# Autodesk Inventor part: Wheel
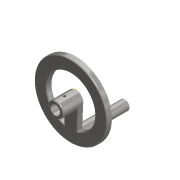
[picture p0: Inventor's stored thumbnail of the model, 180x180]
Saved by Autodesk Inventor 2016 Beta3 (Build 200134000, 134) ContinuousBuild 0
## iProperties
Created: 2016-02
Part Number: Wheel
Material: Stainless Steel
Document SubType Name: Modeling
Designer: Vertex
Density: 8 g/cm^3
Appearance: Semi-Polished
Mass: 759.354 g
Surface Area: 286.814 cm^2
Volume: 94.9192 cm^3
Author: Vertex
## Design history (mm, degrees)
sketch "Sketch1"
  geometry: C1 r 12.5 at (0, 0); 1 further point
  constraints: 1 centre point
  dimensions: "d1" = 25 diameter of C1
extrude "Extrusion1" new body sketch "Sketch1" distance "d2" = 35; taper "d3" = 0 deg
hole "Hole1" diameter "d6" = 16; stored, may be unused: countersink angle "d10" = 90 deg, drill point angle "d12" = 118 deg; dims "d4" = 10, "d5" = 10, "d7" = 7.5, "d8" = 3.75, "d9" = 2.5, "d11" = 30
workplane "Work Plane1"
sketch "Sketch2"
  geometry: L1 (12.5, 35)-(-12.5, 35) reference; C1 r 2.5 at (0, 20); 1 further point
  constraints: 1 centre point
  dimensions: "d14" = 5 diameter of C1; "d15" = 15 distance from line of C1.centre L1
hole "Hole2" sketch "Sketch2" at (0, 20) diameter "d16" = 4.13; stored, may be unused: countersink angle "d20" = 90 deg, drill point angle "d22" = 118 deg; dims "d17" = 10, "d18" = 3.75, "d19" = 2.5, "d21" = 10
sketch "Sketch3"
  geometry: 1 further point
sketch "Sketch4" dims "d29" = 120 (derived)
  geometry: L1 (10.877, -38.493)-(12.489, -0.523); L2 (-10.9, -38.486)-(-12.489, -0.523); A1 r 12.5 centre (0, 0) between (12.489, -0.53) and (-12.489, -0.523); A2 r 40 centre (0, 0) between (10.877, -38.493) and (-10.9, -38.486); 4 further points
  constraints: 5 point on circle, 4 end point, 3 coincident, 2 centre point, 2 vertical alignment, 1 horizontal alignment, 1 point on line, 7 other
  dimensions: "d27" = 60 distance of point (0, 0) point (0, -60); "d30" = 80 diameter of A2; "d31" = 21.77766 distance of L1.start L2.start
extrude "Extrusion2" join sketch "Sketch4" distance "d32" = 10; taper "d33" = 0 deg
fillet "Fillet1" dims "d34" = 2
sketch "Sketch5"
  geometry: C1 r 8 at (0, -50); 1 further point
  constraints: 1 centre point
  dimensions: "d35" = 16 diameter of C1
extrude "Extrusion3" join sketch "Sketch5" distance "d36" = 80; taper "d37" = 0 deg
sketch "Sketch6"
  geometry: C1 r 2.5 at (0, 0); 1 further point
  constraints: 1 centre point
  dimensions: "d38" = 5 diameter of C1
hole "Hole3" sketch "Sketch6" at (0, 0) diameter "d39" = 4.13; stored, may be unused: countersink angle "d43" = 90 deg, drill point angle "d45" = 118 deg; dims "d40" = 10, "d41" = 3.75, "d42" = 2.5, "d44" = 20
body "Solid1"
other parameters: "d13" = 12.5
